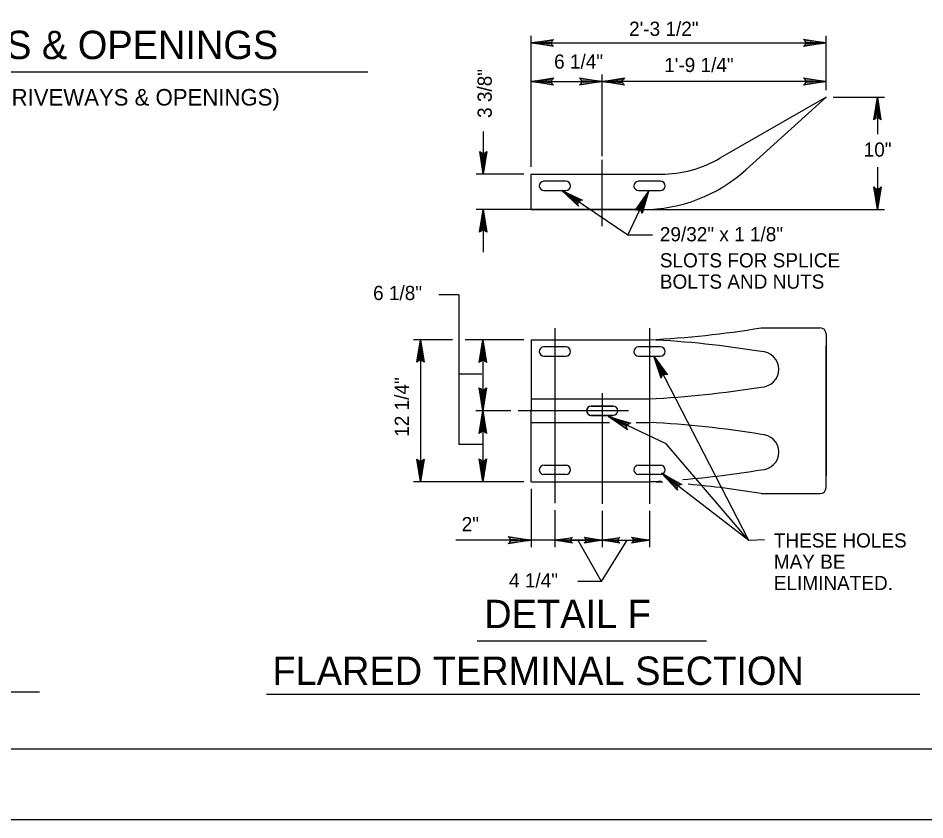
# Model space of a CAD drawing. Extents: x 637628 to 640188, y 298266 to 300751.
# Drawn here: x 638462.3 to 638654, y 298265.6 to 298435 of the extents above; entities that cross this region are included whole.
import ezdxf

# ---------------------------------------------------------------- set-up
doc = ezdxf.new("R2010")
doc.units = 0
for name, color, linetype in [('1', 7, 'Continuous'), ('2', 7, 'Continuous'), ('3', 7, 'Continuous'), ('PLT-BNDY', 7, 'Continuous')]:
    doc.layers.add(name, color=color, linetype=linetype)

msp = doc.modelspace()

# ---------------------------------------------------------------- linework, layer by layer
at = {"layer": '1'}
for q in [(638580.65, 298324.73), (638591.05, 298324.67)]:
    msp.add_line((638585.62, 298315.96), q, dxfattribs=at)
for points in [[(639104.52, 298280.58), (639104.52, 298844.55), (638318.55, 298844.55), (638318.55, 298280.58), (639104.52, 298280.58), (639104.52, 298306.93), (638904.53, 298306.93), (638904.53, 298371.61), (639104.52, 298371.61), (639104.52, 298400.57), (638904.53, 298400.57), (638904.53, 298280.58), (638983.33, 298280.58), (638983.33, 298306.93), (638983.33, 298280.58), (639060.33, 298280.58), (639060.33, 298306.93), (639060.33, 298294.62), (639104.52, 298294.62)], [(638560.01, 298362.43), (638560.34, 298362.6), (638560.59, 298367.04), (638560.01, 298362.43), (638559.8, 298362.19), (638560.59, 298367.04), (638560.81, 298362.6), (638561.14, 298362.44), (638560.59, 298367.04), (638561.36, 298362.19), (638561.14, 298362.44)], [(638598.33, 298359.2), (638598.54, 298359.5), (638596.73, 298363.57), (638598.33, 298359.2), (638598.25, 298358.9), (638596.73, 298363.57), (638598.96, 298359.72), (638599.32, 298359.73), (638596.73, 298363.57), (638599.63, 298359.61), (638599.32, 298359.73)], [(638561.17, 298356.66), (638560.83, 298356.48), (638560.59, 298352.04), (638561.17, 298356.66), (638561.37, 298356.89), (638560.59, 298352.04), (638560.37, 298356.48), (638560.04, 298356.64), (638560.59, 298352.04), (638559.82, 298356.89), (638560.04, 298356.64)], [(638560.01, 298347.43), (638560.34, 298347.6), (638560.59, 298352.04), (638560.01, 298347.43), (638559.8, 298347.19), (638560.59, 298352.04), (638560.81, 298347.6), (638561.14, 298347.44), (638560.59, 298352.04), (638561.36, 298347.19), (638561.14, 298347.44)], [(638591.03, 298348.29), (638591.02, 298348.67), (638587.11, 298350.78), (638591.03, 298348.29), (638591.16, 298348.01), (638587.11, 298350.78), (638591.22, 298349.09), (638591.5, 298349.32), (638587.11, 298350.78), (638591.82, 298349.41), (638591.5, 298349.32)], [(638561.17, 298341.66), (638560.83, 298341.48), (638560.59, 298337.04), (638561.17, 298341.66), (638561.37, 298341.89), (638560.59, 298337.04), (638560.37, 298341.48), (638560.04, 298341.64), (638560.59, 298337.04), (638559.82, 298341.89), (638560.04, 298341.64)], [(638601.64, 298335.55), (638601.7, 298335.92), (638598.34, 298338.82), (638601.64, 298335.55), (638601.7, 298335.25), (638598.34, 298338.82), (638601.99, 298336.29), (638602.32, 298336.45), (638598.34, 298338.82), (638602.65, 298336.47), (638602.32, 298336.45)], [(638566.14, 298325.25), (638566.32, 298324.92), (638570.76, 298324.67), (638566.14, 298325.25), (638565.91, 298325.46), (638570.76, 298324.67), (638566.32, 298324.45), (638566.16, 298324.12), (638570.76, 298324.67), (638565.91, 298323.9), (638566.16, 298324.12)], [(638579.31, 298324.23), (638579.18, 298324.48), (638575.76, 298324.67), (638579.31, 298324.23), (638579.49, 298324.07), (638575.76, 298324.67), (638579.17, 298324.84), (638579.3, 298325.1), (638575.76, 298324.67), (638579.49, 298325.27), (638579.3, 298325.1)], [(638582.2, 298325.12), (638582.34, 298324.86), (638585.76, 298324.67), (638582.2, 298325.12), (638582.02, 298325.28), (638585.76, 298324.67), (638582.34, 298324.5), (638582.22, 298324.25), (638585.76, 298324.67), (638582.02, 298324.08), (638582.22, 298324.25)], [(638589.31, 298324.23), (638589.18, 298324.48), (638585.76, 298324.67), (638589.31, 298324.23), (638589.49, 298324.07), (638585.76, 298324.67), (638589.17, 298324.84), (638589.3, 298325.1), (638585.76, 298324.67), (638589.49, 298325.27), (638589.3, 298325.1)], [(638592.2, 298325.12), (638592.34, 298324.86), (638595.76, 298324.67), (638592.2, 298325.12), (638592.02, 298325.28), (638595.76, 298324.67), (638592.34, 298324.5), (638592.22, 298324.25), (638595.76, 298324.67), (638592.02, 298324.08), (638592.22, 298324.25)]]:
    msp.add_lwpolyline(points, dxfattribs=at)
at = {"layer": '2'}
for p, q in [((638570.76, 298403.54), (638570.76, 298431.25)), ((638633.12, 298419.79), (638633.12, 298431.25)), ((638570.76, 298429.75), (638633.12, 298429.75)), ((638585.76, 298405.81), (638585.76, 298423.09)), ((638570.76, 298421.59), (638585.76, 298421.59)), ((638633.12, 298421.59), (638585.76, 298421.59)), ((638633.12, 298418.29), (638610.69, 298405.38)), ((638633.12, 298418.29), (638616.15, 298402.94)), ((638634.62, 298418.29), (638645.47, 298418.29)), ((638643.97, 298418.29), (638643.97, 298410.45)), ((638560.65, 298411.04), (638560.65, 298402.04)), ((638585.76, 298391.04), (638585.76, 298405.02)), ((638569.26, 298402.04), (638559.15, 298402.04)), ((638570.76, 298394.54), (638570.76, 298402.04)), ((638570.76, 298402.04), (638598.21, 298402.04)), ((638643.97, 298403.5), (638643.97, 298394.54)), ((638578.1, 298400.53), (638573.41, 298400.53)), ((638598.1, 298400.53), (638593.41, 298400.53)), ((638573.49, 298398.55), (638578.1, 298398.55)), ((638575.76, 298399.54), (638575.76, 298399.54)), ((638591.19, 298389.16), (638577.23, 298398.55)), ((638593.49, 298398.55), (638598.1, 298398.55)), ((638595.76, 298399.54), (638595.76, 298399.54)), ((638592.85, 298394.54), (638559.15, 298394.54)), ((638560.65, 298394.54), (638560.65, 298385.54)), ((638570.76, 298394.54), (638594.35, 298394.54)), ((638595.85, 298394.54), (638645.47, 298394.54)), ((638596.43, 298389.16), (638591.19, 298389.16)), ((638555.46, 298376.51), (638551.27, 298376.51)), ((638555.46, 298376.51), (638555.46, 298344.87)), ((638575.76, 298369.47), (638575.76, 298332.5)), ((638595.76, 298369.47), (638595.76, 298332.37)), ((638619.37, 298369.54), (638631.87, 298369.54)), ((638631.87, 298369.54), (638631.87, 298369.54)), ((638633.12, 298368.29), (638633.12, 298338.29)), ((638554.13, 298367.04), (638545.89, 298367.04)), ((638547.39, 298367.04), (638547.39, 298337.04)), ((638569.26, 298367.04), (638556.82, 298367.04)), ((638569.26, 298367.04), (638559.09, 298367.04)), ((638560.59, 298367.04), (638560.59, 298352.04)), ((638570.76, 298367.04), (638595.76, 298367.04)), ((638570.76, 298367.04), (638570.76, 298352.04)), ((638570.76, 298367.04), (638570.76, 298367.04)), ((638633.12, 298335.79), (638633.12, 298365.79)), ((638578.1, 298365.53), (638573.41, 298365.53)), ((638575.76, 298364.54), (638575.76, 298364.54)), ((638575.76, 298364.54), (638575.76, 298364.54)), ((638598.1, 298365.53), (638593.41, 298365.53)), ((638595.76, 298364.54), (638595.76, 298364.54)), ((638595.76, 298364.54), (638595.76, 298364.54)), ((638573.49, 298363.55), (638578.1, 298363.55)), ((638593.49, 298363.55), (638598.1, 298363.55)), ((638560.36, 298359.73), (638555.46, 298359.73)), ((638570.76, 298354.54), (638595.76, 298354.54)), ((638585.76, 298355.73), (638585.76, 298332.37)), ((638610.62, 298355.79), (638610.62, 298355.79)), ((638588.1, 298353.03), (638583.41, 298353.03)), ((638583.49, 298353.03), (638588.1, 298353.03)), ((638566.51, 298352.04), (638559.09, 298352.04)), ((638560.59, 298352.04), (638560.59, 298337.04)), ((638591.37, 298352.04), (638568.01, 298352.04)), ((638570.76, 298337.04), (638570.76, 298352.04)), ((638588.1, 298351.05), (638583.41, 298351.05)), ((638583.49, 298351.05), (638588.1, 298351.05)), ((638585.76, 298352.04), (638585.76, 298352.04)), ((638585.76, 298352.04), (638585.76, 298352.04)), ((638570.76, 298349.54), (638587.32, 298349.54)), ((638592.95, 298349.54), (638595.76, 298349.54)), ((638610.62, 298348.29), (638610.62, 298348.29)), ((638560.48, 298344.87), (638555.46, 298344.87)), ((638573.49, 298340.53), (638578.1, 298340.53)), ((638575.76, 298339.54), (638575.76, 298339.54)), ((638575.76, 298339.54), (638575.76, 298339.54)), ((638593.49, 298340.53), (638598.1, 298340.53)), ((638595.76, 298339.54), (638595.76, 298339.54)), ((638595.76, 298339.54), (638595.76, 298339.54)), ((638569.26, 298337.04), (638545.89, 298337.04)), ((638569.26, 298337.04), (638559.09, 298337.04)), ((638570.76, 298337.04), (638595.76, 298337.04)), ((638570.76, 298337.04), (638570.76, 298337.04)), ((638578.1, 298338.55), (638573.41, 298338.55)), ((638598.1, 298338.55), (638593.41, 298338.55)), ((638570.76, 298335.54), (638570.76, 298323.17)), ((638619.37, 298334.54), (638631.87, 298334.54)), ((638631.87, 298334.54), (638631.87, 298334.54)), ((638575.76, 298331), (638575.76, 298323.17)), ((638585.76, 298330.87), (638585.76, 298323.17)), ((638595.76, 298330.87), (638595.76, 298323.17)), ((638570.76, 298324.67), (638554.85, 298324.67)), ((638575.76, 298324.67), (638570.76, 298324.67)), ((638585.76, 298324.67), (638575.76, 298324.67)), ((638575.76, 298324.67), (638584.76, 298324.67)), ((638585.76, 298324.67), (638595.76, 298324.67)), ((638585.62, 298315.96), (638580.62, 298315.96))]:
    msp.add_line(p, q, dxfattribs=at)
for points in [[(638575.3, 298429.18), (638575.13, 298429.51), (638570.76, 298429.75), (638575.3, 298429.18), (638575.53, 298428.98), (638570.76, 298429.75), (638575.12, 298429.97), (638575.28, 298430.29), (638570.76, 298429.75), (638575.53, 298430.51), (638575.28, 298430.29)], [(638628.58, 298430.32), (638628.75, 298429.99), (638633.12, 298429.75), (638628.58, 298430.32), (638628.34, 298430.52), (638633.12, 298429.75), (638628.75, 298429.53), (638628.59, 298429.21), (638633.12, 298429.75), (638628.34, 298428.99), (638628.59, 298429.21)], [(638575.3, 298421.02), (638575.13, 298421.35), (638570.76, 298421.59), (638575.3, 298421.02), (638575.53, 298420.82), (638570.76, 298421.59), (638575.12, 298421.8), (638575.28, 298422.13), (638570.76, 298421.59), (638575.53, 298422.35), (638575.28, 298422.13)], [(638581.22, 298422.16), (638581.38, 298421.83), (638585.76, 298421.59), (638581.22, 298422.16), (638580.98, 298422.36), (638585.76, 298421.59), (638581.39, 298421.37), (638581.23, 298421.05), (638585.76, 298421.59), (638580.98, 298420.83), (638581.23, 298421.05)], [(638590.3, 298421.02), (638590.13, 298421.35), (638585.76, 298421.59), (638590.3, 298421.02), (638590.53, 298420.82), (638585.76, 298421.59), (638590.12, 298421.8), (638590.28, 298422.13), (638585.76, 298421.59), (638590.53, 298422.35), (638590.28, 298422.13)], [(638628.58, 298422.16), (638628.75, 298421.83), (638633.12, 298421.59), (638628.58, 298422.16), (638628.34, 298422.36), (638633.12, 298421.59), (638628.75, 298421.37), (638628.59, 298421.05), (638633.12, 298421.59), (638628.34, 298420.83), (638628.59, 298421.05)], [(638643.4, 298413.75), (638643.73, 298413.92), (638643.97, 298418.29), (638643.4, 298413.75), (638643.2, 298413.52), (638643.97, 298418.29), (638644.19, 298413.92), (638644.51, 298413.76), (638643.97, 298418.29), (638644.73, 298413.52), (638644.51, 298413.76)], [(638561.23, 298406.58), (638560.9, 298406.41), (638560.65, 298402.04), (638561.23, 298406.58), (638561.42, 298406.82), (638560.65, 298402.04), (638560.44, 298406.41), (638560.11, 298406.57), (638560.65, 298402.04), (638559.9, 298406.82), (638560.11, 298406.57)], [(638580.67, 298395.54), (638580.72, 298395.91), (638577.23, 298398.55), (638580.67, 298395.54), (638580.75, 298395.24), (638577.23, 298398.55), (638580.97, 298396.29), (638581.28, 298396.47), (638577.23, 298398.55), (638581.61, 298396.51), (638581.28, 298396.47)], [(638591.19, 298389.16), (638595.59, 298398.36)], [(638593.12, 298394.51), (638593.49, 298394.52), (638595.59, 298398.36), (638593.12, 298394.51), (638592.84, 298394.39), (638595.59, 298398.36), (638593.9, 298394.33), (638594.13, 298394.04), (638595.59, 298398.36), (638594.22, 298393.73), (638594.13, 298394.04)], [(638644.54, 298399.08), (638644.21, 298398.91), (638643.97, 298394.54), (638644.54, 298399.08), (638644.74, 298399.32), (638643.97, 298394.54), (638643.75, 298398.91), (638643.43, 298399.07), (638643.97, 298394.54), (638643.21, 298399.32), (638643.43, 298399.07)], [(638560.08, 298390), (638560.41, 298390.17), (638560.65, 298394.54), (638560.08, 298390), (638559.89, 298389.77), (638560.65, 298394.54), (638560.87, 298390.17), (638561.2, 298390.01), (638560.65, 298394.54), (638561.41, 298389.77), (638561.2, 298390.01)], [(638546.82, 298362.5), (638547.15, 298362.67), (638547.39, 298367.04), (638546.82, 298362.5), (638546.62, 298362.27), (638547.39, 298367.04), (638547.61, 298362.67), (638547.93, 298362.51), (638547.39, 298367.04), (638548.15, 298362.27), (638547.93, 298362.51)], [(638616.78, 298324.62), (638596.73, 298363.57)], [(638616.78, 298324.62), (638599.34, 298345.01), (638587.11, 298350.78)], [(638547.96, 298341.58), (638547.63, 298341.41), (638547.39, 298337.04), (638547.96, 298341.58), (638548.16, 298341.82), (638547.39, 298337.04), (638547.18, 298341.41), (638546.85, 298341.57), (638547.39, 298337.04), (638546.63, 298341.82), (638546.85, 298341.57)], [(638620.08, 298324.75), (638616.78, 298324.62), (638598.34, 298338.82)]]:
    msp.add_lwpolyline(points, dxfattribs=at)
for centre, radius, start, end in [((638598.21, 298427.04), 25, 270, 299.9315), ((638594.35, 298427.04), 32.5, 270, 312.1381), ((638573.48, 298399.54), 0.989, 93.1764, 271.2759), ((638578.09, 298399.54), 0.989, 270.6286, 88.7414), ((638593.48, 298399.54), 0.989, 93.1764, 271.2759), ((638598.09, 298399.54), 0.989, 270.6286, 88.7414), ((638586.03, 298571.65), 204.84, 272.721, 279.3664), ((638631.87, 298368.29), 1.25, 0, 90), ((638586.03, 298162.43), 204.84, 80.6336, 87.279), ((638573.48, 298364.54), 0.989, 93.1764, 271.2759), ((638578.09, 298364.54), 0.989, 270.6286, 88.7414), ((638593.48, 298364.54), 0.989, 93.1764, 271.2759), ((638598.09, 298364.54), 0.989, 270.6286, 88.7414), ((638619.37, 298360.79), 3.75, 270, 90), ((638586.03, 298559.15), 204.84, 272.721, 279.3664), ((638583.48, 298352.04), 0.989, 88.7241, 266.8236), ((638583.48, 298352.04), 0.989, 93.1764, 271.2759), ((638588.09, 298352.04), 0.989, 271.2586, 89.3714), ((638588.09, 298352.04), 0.989, 270.6286, 88.7414), ((638586.03, 298144.93), 204.84, 80.6336, 87.279), ((638619.37, 298343.29), 3.75, 270, 90), ((638573.48, 298339.54), 0.989, 88.7241, 266.8236), ((638578.09, 298339.54), 0.989, 271.2586, 89.3714), ((638593.48, 298339.54), 0.989, 88.7241, 266.8236), ((638598.09, 298339.54), 0.989, 271.2586, 89.3714), ((638586.03, 298541.65), 204.84, 274.7169, 279.3664), ((638586.03, 298541.65), 204.84, 272.721, 273.4475), ((638586.03, 298132.43), 204.84, 86.4804, 87.279), ((638586.03, 298132.43), 204.84, 80.6336, 84.976), ((638631.87, 298335.79), 1.25, 270, 0)]:
    msp.add_arc(centre, radius, start, end, dxfattribs=at)
at = {"layer": '3'}
for p, q in [((638414.99, 298423.66), (638536.25, 298423.66)), ((638559.35, 298303.43), (638607.87, 298303.43)), ((638326.95, 298292.6), (638466.84, 298292.6)), ((638514.82, 298292.16), (638652.94, 298292.16))]:
    msp.add_line(p, q, dxfattribs=at)
at = {"layer": 'PLT-BNDY'}
msp.add_lwpolyline([(638278.52, 298859.58), (639119.52, 298859.58), (639119.52, 298265.58), (638278.52, 298265.58)], close=True, dxfattribs=at)

# ---------------------------------------------------------------- texts
at = {"layer": '1'}
for s, p in [('6 1/4"', (638575.63, 298424.32)), ('10"', (638641.07, 298405.72)), ('6 1/8"', (638537.36, 298375.42))]:
    msp.add_text(s, height=3, dxfattribs=at).set_placement(p)
msp.add_text('12 1/4"', height=3, rotation=90, dxfattribs=at).set_placement((638544.93, 298346.53))
at = {"layer": '3'}
for s, height, p in [('2\'-3 1/2"', 3, (638591.48, 298431.25)), ('DRIVEWAYS & OPENINGS', 6, (638416.99, 298426.34)), ('1\'-9 1/4"', 3, (638598.9, 298423.6)), ('(USE ON BOTH SIDES OF DRIVEWAYS & OPENINGS)', 3.5, (638399.32, 298416.52)), ('29/32" x 1 1/8"', 3, (638597.98, 298387.83)), ('SLOTS FOR SPLICE', 3, (638597.98, 298382.32)), ('BOLTS AND NUTS', 3, (638597.98, 298377.82)), ('2"', 3, (638556.09, 298326.56)), ('THESE HOLES', 3, (638622.07, 298323.13)), ('MAY BE', 3, (638622.07, 298318.63)), ('4 1/4"', 3, (638566.1, 298314.68)), ('ELIMINATED.', 3, (638622.07, 298314.13)), ('DETAIL F', 6, (638560.86, 298306.09)), ('FLARED TERMINAL SECTION', 6, (638516.08, 298294.09))]:
    msp.add_text(s, height=height, dxfattribs=at).set_placement(p)
msp.add_text('3 3/8"', height=3, rotation=90, dxfattribs=at).set_placement((638562.45, 298413.9))

doc.saveas('drawing.dxf')
